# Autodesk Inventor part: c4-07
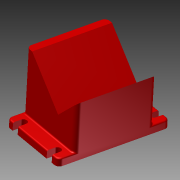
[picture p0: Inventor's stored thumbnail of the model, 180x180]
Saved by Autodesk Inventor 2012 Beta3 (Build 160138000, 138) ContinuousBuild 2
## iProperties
Created: 2010-11
Part Number: c4-07
Material: Default
Document SubType Name: Modeling
Designer: Beta-8540w
Density: 1 g/cm^3
Author: Beta-8540w
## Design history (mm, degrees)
sketch "Sketch1"
  geometry: L1 (-45, 0)-(45, 0); L2 (45, 0)-(45, 10); L3 (45, 10)-(-45, 10); L4 (-45, 10)-(-45, 0); L5 (-45, 10)-(-45, 90); L6 (-45, 90)-(-35, 90); L7 (-35, 90)-(14.497, 40.503); L8 (14.497, 40.503)-(45, 71.005); L9 (45, 71.005)-(45, 10); 2 further points
  constraints: 18 end point, 4 perpendicular, 3 collinear, 2 parallel, 2 point on line, 1 coincident, 1 horizontal, 1 midpoint
  dimensions: "d0" = 90 distance of L3.end L2.end; "d1" = 10 distance of L2.end L1.end; "d2" = 80 distance of L5.start L5.end; "d3" = 10 distance of L5.end L6.end; "d4" = 70 distance of L6.end L7.end; "d5" = 135 deg angle of L6 L7
extrude "Extrusion1" new body sketch "Sketch1" stored distance "d8" = 100; taper "d9" = 0 deg
extrude "Extrusion2" join sketch "Sketch1" stored distance "d10" = 140; taper "d11" = 0 deg
fillet "Fillet1" dims "d12" = 6
fillet "Fillet2" dims "d13" = 2
sketch "Sketch2"
  geometry: L1 (78, -2)-(0, -2) reference; L2 (-6, 4)-(-6, 132) reference; L3 (4.5, -2)-(13.5, -2); L4 (13.5, -2)-(13.5, 8); L5 (13.5, 8)-(4.5, 8); L6 (4.5, 8)-(4.5, -2); 2 further points
  constraints: 8 end point, 2 parallel, 1 horizontal, 1 horizontal alignment, 1 midpoint, 1 perpendicular, 1 point on line, 2 other
  dimensions: "d14" = 9 distance of L5.end L4.end; "d15" = 10 distance of L4.end L3.end; "d16" = 15 distance from line of point (9, 8) L2
extrude "Extrusion3" cut sketch "Sketch2" stored distance "d17" = 140; taper "d18" = 0 deg
mirror "Mirror1"
mirror "Mirror2"
body "Solid1"
